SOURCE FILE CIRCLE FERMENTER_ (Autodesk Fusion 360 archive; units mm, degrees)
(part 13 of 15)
sketch "Sketch1" plane through (0, 0, 0) normal (0, 1, 0) x axis (1, 0, 0)
  line L1 (-1.5, 8) -> (-1.5, 0)
  line L2 (0, 8) -> (-1.5, 8)
  line L3 (0, -3) -> (0, 8)
  line L4 (-2.75, 0) -> (-1.5, 0)
  line L5 (-2.75, -3) -> (-2.75, 0)
  line L6 (0, -3) -> (-2.75, -3)
  point P1 (0, 0)
  point P4 (0, 8)
  point P7 (0, -3)
  point P5 (-2.75, 0)
  point P6 (-2.75, -3)
  perpendicular L1 L2
  collinear P1 P4 P7
  perpendicular L1 L4
  coincident P1 L4
  vertical L1
  vertical L3
  parallel L3 L5
  coincident L3 P7
  perpendicular L3 L6
  dimension "d9" = 3 (= "adsk_nomdia")
  dimension "d66" = 5.5 (= "adsk_headdia")
  dimension "d68" distance P1 P4 = 8 (= "adsk_nomlen")
  dimension "d79" distance P5 P6 = 3 (= "adsk_headh")
revolve "Revolve1" sketch "Sketch1" AlongAngle 360
work_plane "WorkPlane1" AlongDistance 3 (= "adsk_headh")
sketch "Sketch6" plane through (0, 0, 3) normal (0, 0, 1) x axis (1, 0, 0)
  line L1 (1.25, 0) -> (-1.25, 0)
  line L2 (-1.25, 0.7217) -> (0, 0)
  line L3 (-1.25, 0.7217) -> (-1.25, -0.7217)
  line L4 (0, 0) -> (-1.25, -0.7217)
  point P1 (0, 0)
  point P4 (0, 0)
  point P2 (-1.25, 0)
  point P5 (-1.25, 0.7217)
  point P7 (-1.25, 0.7217)
  point P8 (0, 0)
  point P3 (1.25, 0)
  horizontal L1
  midpoint P1 L1
  coincident P1 P4
  perpendicular L1 L3
  midpoint P2 L3
  coincident P5 P7
  coincident P1 P8
  dimension "d72" distance P2 P3 = 2.5 (= "adsk_waflat")
  dimension "d100" angle L1 L2 = 150
extrude "Extrude1" cut sketch "Sketch6" profile of L2 L3 L4 no distance stored
circular_pattern "C-Pattern1" TotalAngle 360
extrude "Extrude2" cut of existing geometry no distance stored taper -85
thread "Thread2" ThreadOffset 0 ThreadLength 6.6933 (= "adsk_thrlen")
fillet "Fillet4" radius 0.3 (= "adsk_nomdia * 0.1")
sketch "Sketch7" plane through (0, 0, 0) normal (0, 1, 0) x axis (1, 0, 0)
  line L1 (-1.53, 7.6933) -> (-1.53, 8)
  line L2 (-1.1933, 8) -> (-1.53, 7.6933)
  line L3 (0, -3) -> (0, 8)
  line L4 (0, 8) -> (-1.53, 8)
  point P5 (0, 8)
  point P7 (0, 8)
  point P4 (-1.1933, 8)
  point P3 (-1.53, 7.6933)
  point P1 (0, 0)
  coincident P5 P7
  perpendicular L3 L4
  coincident P4 L4
  perpendicular L1 L4
  dimension "d92" distance P3 P4 = 0.3067 (= "adsk_startlen")
  dimension "d98" distance P1 P4 = 1.1933 (= "adsk_endpointdia / 2")
  dimension "d99" distance P1 L1 = 1.53 (= "adsk_nomdia * 0.51")
revolve "Revolve3" sketch "Sketch7" AlongAngle 360
joint_origin "JointOrigin2" OffsetX 0 OffsetY 0 OffsetZ 0 AngleZ 0

design "ruthex_RX-M3x4"
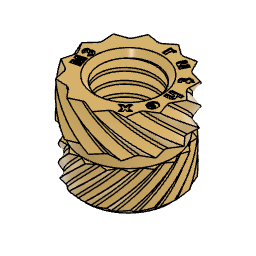
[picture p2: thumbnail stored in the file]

design "PTC"
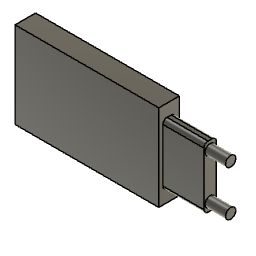
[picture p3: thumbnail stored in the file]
sketch "Schizzo1" plane through (0, 0, 0) normal (0, 1, 0) x axis (1, 0, 0)
  line L1 (35, 0) -> (0, 0)
  line L2 (35, -21) -> (35, 0)
  line L3 (0, -21) -> (35, -21)
  line L4 (0, 0) -> (0, -21)
  point P1 (0, 0)
  point P2 (0, 0)
  point P4 (35, -21)
  point P5 (0, -21)
  horizontal L1
  vertical L2
  horizontal L3
  vertical L4
  coincident P1 P2
  dimension "d19" distance P4 P5 = 35
  dimension "d20" distance P2 P5 = 21
extrude "Estrusione1" new body sketch "Schizzo1" along normal blind 5
sketch "Schizzo2" plane through (35, 0, 0) normal (1, 0, 0) x axis (0, 1, 0)
  line L1 (0, 0) -> (0, 21)
  line L2 (5, 0) -> (0, 0)
  line L3 (5, 21) -> (5, 0)
  line L4 (0, 21) -> (5, 21)
  line L5 (5, 0) -> (0, 21)
  line L6 (0, 0) -> (5, 21)
  line L7 (4, 3) -> (1, 3)
  line L8 (4, 18) -> (4, 3)
  line L9 (1, 18) -> (4, 18)
  line L10 (1, 3) -> (1, 18)
  line L11 (4, 18) -> (1, 3)
  line L12 (1, 18) -> (4, 3)
  point P2 (0, 21)
  point P6 (0, 21)
  point P4 (5, 0)
  point P7 (5, 0)
  point P5 (5, 21)
  point P8 (5, 21)
  point P3 (0, 0)
  point P9 (0, 0)
  point P14 (2.5, 10.5)
  point P10 (1, 3)
  point P11 (4, 3)
  point P13 (1, 18)
  coincident P2 P6
  coincident P4 P7
  coincident P5 P8
  coincident P3 P9
  horizontal L7
  perpendicular L7 L8
  parallel L7 L9
  parallel L8 L10
  coincident L11 P14
  coincident L12 P14
  coincident L5 P14
  coincident L6 P14
  dimension "d23" distance P10 P11 = 3
  dimension "d24" distance P10 P13 = 15
extrude "Estrusione2" add sketch "Schizzo2" profile of L7 L8 L9 L10 along normal blind 10
fillet "Raccordo" radius 1
sketch "Schizzo3" plane through (45, 0, 0) normal (1, 0, 0) x axis (0, 1, 0)
  line L1 (4, 17) -> (4, 4)
  line L2 (2, 18) -> (3, 18)
  line L3 (1, 4) -> (1, 17)
  line L4 (3, 3) -> (2, 3)
  line L5 (2, 4) -> (3, 4)
  line L6 (1, 10.5) -> (4, 10.5)
  line L7 (2.5, 5) -> (2.5, 4)
  arc A1 centre (3, 4) radius 1 clockwise from (4, 4) to (3, 3)
  arc A2 centre (3, 17) radius 1 clockwise from (3, 18) to (4, 17)
  arc A3 centre (2, 17) radius 1 clockwise from (1, 17) to (2, 18)
  arc A4 centre (2, 4) radius 1 clockwise from (2, 3) to (1, 4)
  circle C1 centre (2.5, 5) radius 1.25
  circle C2 centre (2.5, 16) radius 1.25
  point P4 (3, 4)
  point P14 (3, 4)
  point P13 (2, 4)
  point P15 (2, 4)
  point P16 (4, 10.5)
  point P17 (1, 10.5)
  point P19 (2.5, 4)
  point P18 (2.5, 5)
  point P20 (2.5, 5)
  coincident P4 P14
  coincident P13 P15
  midpoint L1 P16
  midpoint L3 P17
  midpoint L5 P19
  coincident P18 P20
  vertical L7
  symmetric L6 C1 C2
  dimension "d29" diameter C1 = 2.5
  dimension "d30" distance P19 P20 = 1
extrude "Estrusione3" add sketch "Schizzo3" profile of C1 C2 along normal blind 5

design "40x40x10 DC Fan"
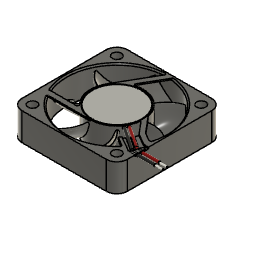
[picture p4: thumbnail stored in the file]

design "GN 1-4 h65.ipt"
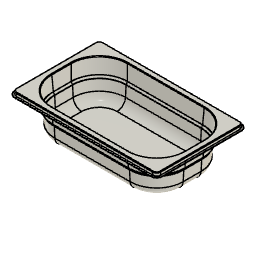
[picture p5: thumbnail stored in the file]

design "Schermo elink"
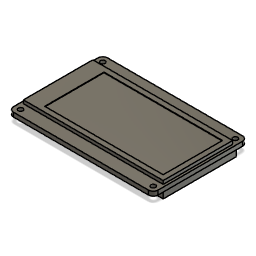
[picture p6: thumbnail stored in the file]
sketch "Schizzo1" plane through (0, 0, 0) normal (0, 1, 0) x axis (1, 0, 0)
  line L1 (-28.5, 19.85) -> (28.5, 19.85)
  line L2 (-30.5, -17.85) -> (-30.5, 17.85)
  line L3 (28.5, -19.85) -> (-28.5, -19.85)
  line L4 (30.5, 17.85) -> (30.5, -17.85)
  line L5 (-30.5, -19.85) -> (30.5, 19.85)
  line L6 (30.5, -19.85) -> (-30.5, 19.85)
  line L7 (28, 17.35) -> (-28, 17.35)
  line L8 (28, -17.35) -> (28, 17.35)
  line L9 (-28, -17.35) -> (28, -17.35)
  line L10 (-28, 17.35) -> (-28, -17.35)
  line L11 (28, -17.35) -> (-28, 17.35)
  line L12 (-28, -17.35) -> (28, 17.35)
  line L13 (29.5, 14.65) -> (-29.5, 14.65)
  line L14 (29.5, -14.65) -> (29.5, 14.65)
  line L15 (-29.5, -14.65) -> (29.5, -14.65)
  line L16 (-29.5, 14.65) -> (-29.5, -14.65)
  line L17 (29.5, -14.65) -> (-29.5, 14.65)
  line L18 (-29.5, -14.65) -> (29.5, 14.65)
  line L19 (-22.65, 12.5) -> (27.35, 12.5)
  line L20 (-22.65, -12.5) -> (-22.65, 12.5)
  line L21 (27.35, -12.5) -> (-22.65, -12.5)
  line L22 (27.35, 12.5) -> (27.35, -12.5)
  circle C1 centre (-28, 17.35) radius 1
  circle C2 centre (28, 17.35) radius 1
  circle C3 centre (-28, -17.35) radius 1
  circle C4 centre (28, -17.35) radius 1
  arc A1 centre (28.5, 17.85) radius 2 clockwise from (28.5, 19.85) to (30.5, 17.85)
  arc A2 centre (28.5, -17.85) radius 2 clockwise from (30.5, -17.85) to (28.5, -19.85)
  arc A3 centre (-28.5, -17.85) radius 2 clockwise from (-28.5, -19.85) to (-30.5, -17.85)
  arc A4 centre (-28.5, 17.85) radius 2 clockwise from (-30.5, 17.85) to (-28.5, 19.85)
  point P6 (0, 0)
  point P1 (0, 0)
  point P11 (0, 0)
  point P7 (-28, 17.35)
  point P12 (-28, 17.35)
  point P20 (0, 0)
  point P2 (30.5, 19.85)
  point P5 (30.5, -19.85)
  point P4 (-30.5, -19.85)
  point P3 (-30.5, 19.85)
  point P16 (-29.5, 14.65)
  point P19 (-29.5, -14.65)
  point P17 (29.5, 14.65)
  point P21 (27.35, 12.5)
  point P22 (-22.65, 12.5)
  point P24 (27.35, -12.5)
  horizontal L1
  perpendicular L1 L2
  parallel L1 L3
  parallel L2 L4
  coincident L5 P6
  coincident L6 P6
  coincident P1 P6
  horizontal L7
  perpendicular L7 L8
  parallel L7 L9
  parallel L8 L10
  coincident L11 P11
  coincident L12 P11
  coincident P1 P11
  coincident P7 P12
  horizontal L13
  perpendicular L13 L14
  parallel L13 L15
  parallel L14 L16
  coincident L17 P20
  coincident L18 P20
  coincident P1 P20
  horizontal L19
  vertical L20
  horizontal L21
  vertical L22
  coincident P2 L1
  coincident P2 L4
  tangent L1 A1
  tangent L4 A1
  coincident P5 L3
  coincident P5 L4
  tangent L3 A2
  tangent L4 A2
  equal A1 A2
  coincident P4 L2
  coincident P4 L3
  tangent L2 A3
  tangent L3 A3
  equal A1 A3
  coincident P3 L2
  coincident P3 L1
  tangent L2 A4
  tangent L1 A4
  equal A1 A4
  dimension "d1" distance P4 P5 = 61
  dimension "d2" distance P2 P5 = 39.7
  dimension "d3" diameter C1 = 2
  dimension "d4" distance L1 P12 = 2.5 (= "d5")
  dimension "d5" distance L2 L10 = 2.5
  dimension "d11" distance P16 P19 = 29.3
  dimension "d12" distance P16 P17 = 59
  dimension "d13" distance P21 P22 = 50
  dimension "d14" distance P21 P24 = 25
  dimension "d15" distance L13 L19 = 2.15
  dimension "d16" distance L14 L22 = 2.15
  dimension "d17" radius A1 = 2
  dimension "d9" R-Pattern1-uDistance = 56
  dimension "d10" R-Pattern1-vDistance = -34.7
extrude "Estrusione1" new body sketch "Schizzo1" profile of L1 L2 L3 L4 C1 C2 C3 C4 L13 L14 L15 L16 L19 L20 L21 L22 A1 A2 A3 A4 against normal blind 1.8 bodies "scheda"
extrude "Estrusione2" new body sketch "Schizzo1" profile of L13 L14 L15 L16 L19 L20 L21 L22 along normal blind 1.4 bodies "Schermo"
extrude "Estrusione3" sketch "Schizzo1" profile of L19 L20 L21 L22 blind -0.2
sketch "Schizzo2" plane through (0, -1.8, 0) normal (0, -1, 0) x axis (1, 0, 0)
  line L1 (28.5, -19.85) -> (-28.5, -19.85)
  line L2 (30.5, 17.85) -> (30.5, -17.85)
  line L3 (-28.5, 19.85) -> (28.5, 19.85)
  line L4 (-30.5, -17.85) -> (-30.5, 17.85)
  line L5 (30.5, 15.6614) -> (-30.5, 15.6614)
  line L6 (30.5, -15.2284) -> (30.5, 15.6614)
  line L7 (-30.5, -15.2284) -> (30.5, -15.2284)
  line L8 (-30.5, 15.6614) -> (-30.5, -15.2284)
  circle C1 centre (28, 17.35) radius 1
  circle C2 centre (-28, 17.35) radius 1
  circle C3 centre (-28, -17.35) radius 1
  circle C4 centre (28, -17.35) radius 1
  arc A1 centre (-28.5, -17.85) radius 2 clockwise from (-28.5, -19.85) to (-30.5, -17.85)
  arc A2 centre (28.5, -17.85) radius 2 clockwise from (30.5, -17.85) to (28.5, -19.85)
  arc A3 centre (28.5, 17.85) radius 2 clockwise from (28.5, 19.85) to (30.5, 17.85)
  arc A4 centre (-28.5, 17.85) radius 2 clockwise from (-30.5, 17.85) to (-28.5, 19.85)
  point P20 (30.5, -15.2284)
  point P18 (-30.5, 15.6614)
  horizontal L5
  vertical L6
  horizontal L7
  vertical L8
  coincident L2 P20
  coincident L4 P18
extrude "Estrusione4" new body sketch "Schizzo2" + "Schizzo1" profile of S1:L2 S1:L4 S1:L5 S1:L6 S1:L7 S1:L8 blind 2.5 bodies "Ingombri lettori sd etc"
named bodies: "scheda", "Ingombri lettori sd etc", "Schermo"

design "DHT22 Module v3"
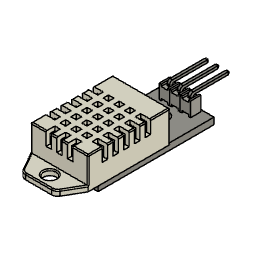
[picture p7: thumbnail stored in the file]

design "MODULO RISCALDATORE 1 ventola" references "PTC", "40x40x10 DC Fan"
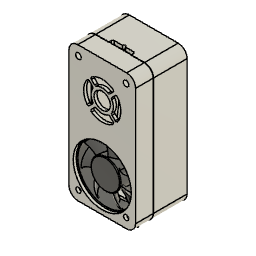
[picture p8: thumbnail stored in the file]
sketch "Schizzo1" plane through (0, 0, 0) normal (0, 1, 0) x axis (1, 0, 0)
  line L1 (40, -20) -> (-40, -20)
  line L2 (40, 20) -> (40, -20)
  line L3 (-40, 20) -> (40, 20)
  line L4 (-40, -20) -> (-40, 20)
  line L5 (40, 20) -> (-40, -20)
  line L6 (-40, 20) -> (40, -20)
  point P6 (0, 0)
  point P1 (0, 0)
  horizontal L1
  perpendicular L1 L2
  parallel L1 L3
  parallel L2 L4
  coincident L5 P6
  coincident L6 P6
  coincident P1 P6
  dimension "d1" distance L2 L4 = 80
  dimension "d2" distance L1 L3 = 40
component_insert "Inserimento componente1"
base_feature "Lavorazione di base1"
joint "Assembla3" alignAngle 0 alignOffsetX 0 alignOffsetY 0 alignOffsetZ 0
sketch "Schizzo3" plane through (0, -5.5864, 0) normal (0, -1, 0) x axis (1, 0, 0)
  line L1 (-79.1534, 19.7854) -> (-47.1534, 19.7854)
  line L2 (-83.1534, -16.2146) -> (-83.1534, 15.7854)
  line L3 (-47.1534, -20.2146) -> (-79.1534, -20.2146)
  line L4 (-43.1534, 15.7854) -> (-43.1534, -16.2146)
  line L5 (-39.1534, 19.7854) -> (-7.1534, 19.7854)
  line L6 (-43.1534, -16.2146) -> (-43.1534, 15.7854)
  line L7 (-7.1534, -20.2146) -> (-39.1534, -20.2146)
  line L8 (-3.1534, 15.7854) -> (-3.1534, -16.2146)
  line L9 (-47.1534, 19.7854) -> (-39.1534, 19.7854)
  line L10 (-47.1534, -20.2146) -> (-39.1534, -20.2146)
  line L11 (-85.1534, -16.2146) -> (-85.1534, 15.7854)
  line L12 (-47.1534, -22.2146) -> (-79.1534, -22.2146)
  line L13 (-47.1534, -22.2146) -> (-39.1534, -22.2146)
  line L14 (-7.1534, -22.2146) -> (-39.1534, -22.2146)
  line L15 (-1.1534, 15.7854) -> (-1.1534, -16.2146)
  line L16 (-39.1534, 21.7854) -> (-7.1534, 21.7854)
  line L17 (-47.1534, 21.7854) -> (-39.1534, 21.7854)
  line L18 (-79.1534, 21.7854) -> (-47.1534, 21.7854)
  line L19 (-1.1534, 67.7854) -> (-1.1534, 15.7854)
  line L20 (-85.1534, 67.7854) -> (-1.1534, 67.7854)
  line L21 (-85.1534, 15.7854) -> (-85.1534, 67.7854)
  arc A1 centre (-47.1534, 15.7854) radius 4 clockwise from (-47.1534, 19.7854) to (-43.1534, 15.7854)
  arc A2 centre (-79.1534, 15.7854) radius 4 clockwise from (-83.1534, 15.7854) to (-79.1534, 19.7854)
  arc A3 centre (-79.1534, -16.2146) radius 4 clockwise from (-79.1534, -20.2146) to (-83.1534, -16.2146)
  arc A4 centre (-47.1534, -16.2146) radius 4 clockwise from (-43.1534, -16.2146) to (-47.1534, -20.2146)
  circle C1 centre (-79.1534, 15.7854) radius 1.725
  circle C2 centre (-79.1534, -16.2146) radius 1.725
  circle C3 centre (-47.1534, -16.2146) radius 1.725
  circle C4 centre (-47.1534, 15.7854) radius 1.725
  circle C5 centre (-63.1534, -0.2146) radius 19.5
  arc A5 centre (-7.1534, 15.7854) radius 4 clockwise from (-7.1534, 19.7854) to (-3.1534, 15.7854)
  arc A6 centre (-39.1534, 15.7854) radius 4 clockwise from (-43.1534, 15.7854) to (-39.1534, 19.7854)
  arc A7 centre (-39.1534, -16.2146) radius 4 clockwise from (-39.1534, -20.2146) to (-43.1534, -16.2146)
  arc A8 centre (-7.1534, -16.2146) radius 4 clockwise from (-3.1534, -16.2146) to (-7.1534, -20.2146)
  circle C6 centre (-39.1534, 15.7854) radius 1.725
  circle C7 centre (-39.1534, -16.2146) radius 1.725
  circle C8 centre (-7.1534, -16.2146) radius 1.725
  circle C9 centre (-7.1534, 15.7854) radius 1.725
  circle C10 centre (-23.1534, -0.2146) radius 19.5
  arc A9 centre (-79.1534, -16.2146) radius 6 clockwise from (-79.1534, -22.2146) to (-85.1534, -16.2146)
  arc A10 centre (-7.1534, -16.2146) radius 6 clockwise from (-1.1534, -16.2146) to (-7.1534, -22.2146)
  point P18 (-39.1534, 19.7854)
  point P28 (-39.1534, 19.7854)
  point P3 (-47.1534, 19.7854)
  point P29 (-47.1534, 19.7854)
  point P22 (-39.1534, -20.2146)
  point P30 (-39.1534, -20.2146)
  point P11 (-47.1534, -20.2146)
  point P31 (-47.1534, -20.2146)
  coincident P18 P28
  coincident P3 P29
  coincident P22 P30
  coincident P11 P31
  concentric A3 A9
  concentric A8 A10
  tangent A9 L12
  tangent L11 A9
  tangent L14 A10
  tangent A10 L15
  parallel L15 L19
  perpendicular L19 L20
  vertical L21
  dimension "d32" distance L12 L20 = 90
extrude "Estrusione2" new body sketch "Schizzo3" profile of A1 L1 A2 L2 A3 L3 A4 L4 C1 C2 C3 C4 C5 A5 L5 A6 L6 A7 L7 A8 L8 C6 C7 C8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 along normal blind 2
fillet "Raccordo1" radius 6
sketch "Schizzo4" plane through (0, -5.5864, 0) normal (0, 1, 0) x axis (-1, 0, 0)
  line L1 (1.1534, -16.2146) -> (1.1534, 61.7854)
  line L2 (79.1534, -22.2146) -> (7.1534, -22.2146)
  line L3 (85.1534, 61.7854) -> (85.1534, -16.2146)
  line L4 (7.1534, 67.7854) -> (79.1534, 67.7854)
  line L5 (7.1534, 65.7854) -> (79.1534, 65.7854)
  line L6 (3.1534, -16.2146) -> (3.1534, 61.7854)
  line L7 (79.1534, -20.2146) -> (7.1534, -20.2146)
  line L8 (83.1534, 61.7854) -> (83.1534, -16.2146)
  circle C1 centre (7.1534, -16.2146) radius 1.725
  circle C2 centre (23.1534, -0.2146) radius 19.5
  circle C3 centre (63.1534, -0.2146) radius 19.5
  circle C4 centre (79.1534, -16.2146) radius 1.725
  arc A1 centre (7.1534, 61.7854) radius 6 clockwise from (1.1534, 61.7854) to (7.1534, 67.7854)
  arc A2 centre (7.1534, -16.2146) radius 6 clockwise from (7.1534, -22.2146) to (1.1534, -16.2146)
  arc A3 centre (79.1534, -16.2146) radius 6 clockwise from (85.1534, -16.2146) to (79.1534, -22.2146)
  arc A4 centre (79.1534, 61.7854) radius 6 clockwise from (79.1534, 67.7854) to (85.1534, 61.7854)
  arc A5 centre (7.1534, 61.7854) radius 4 clockwise from (3.1534, 61.7854) to (7.1534, 65.7854)
  arc A6 centre (7.1534, -16.2146) radius 4 clockwise from (7.1534, -20.2146) to (3.1534, -16.2146)
  arc A7 centre (79.1534, -16.2146) radius 4 clockwise from (83.1534, -16.2146) to (79.1534, -20.2146)
  arc A8 centre (79.1534, 61.7854) radius 4 clockwise from (79.1534, 65.7854) to (83.1534, 61.7854)
  dimension "d37" = -2
extrude "Estrusione3" add sketch "Schizzo4" profile of A1 L1 A2 L2 A3 L3 A4 L4 L5 A8 L7 A5 L6 A6 L8 A7 along normal blind 25
component_insert "Inserimento componente3"
joint "Assembla4" alignAngle 180 alignOffsetX 0 alignOffsetY 0 alignOffsetZ 5
sketch "Schizzo5" plane through (0, -5.5864, 0) normal (0, 1, 0) x axis (-1, 0, 0)
  line L1 (7.1534, 65.7854) -> (79.1534, 65.7854)
  line L2 (3.1534, -16.2146) -> (3.1534, 61.7854)
  line L3 (79.1534, -20.2146) -> (7.1534, -20.2146)
  line L4 (83.1534, 61.7854) -> (83.1534, -16.2146)
  line L5 (47.1534, 19.7854) -> (79.1534, 19.7854)
  line L6 (7.1534, 19.7854) -> (39.1534, 19.7854)
  arc A1 centre (7.1534, 61.7854) radius 4 clockwise from (3.1534, 61.7854) to (7.1534, 65.7854)
  arc A2 centre (7.1534, -16.2146) radius 4 clockwise from (7.1534, -20.2146) to (3.1534, -16.2146)
  arc A3 centre (79.1534, -16.2146) radius 4 clockwise from (83.1534, -16.2146) to (79.1534, -20.2146)
  arc A4 centre (79.1534, 61.7854) radius 4 clockwise from (79.1534, 65.7854) to (83.1534, 61.7854)
  circle C1 centre (7.1534, -16.2146) radius 1.725
  circle C2 centre (63.1534, -0.2146) radius 19.5
  circle C3 centre (79.1534, -16.2146) radius 1.725
  circle C4 centre (23.1534, -0.2146) radius 19.5
sketch "Schizzo6" plane through (0, 0, 67.7854) normal (0, 0, 1) x axis (-1, 0, 0)
  line L1 (7.1534, -19.4136) -> (7.1534, 7.5864)
  line L2 (79.1534, -19.4136) -> (7.1534, -19.4136)
  line L3 (79.1534, 7.5864) -> (79.1534, -19.4136)
  line L4 (7.1534, 7.5864) -> (79.1534, 7.5864)
  line L5 (49.6534, -7.4136) -> (36.6534, -7.4136)
  line L6 (50.6534, -5.4136) -> (50.6534, -6.4136)
  line L7 (36.6534, -4.4136) -> (49.6534, -4.4136)
  line L8 (35.6534, -6.4136) -> (35.6534, -5.4136)
  line L9 (50.6534, -19.4136) -> (50.6534, -6.4136)
  line L10 (35.6534, -19.4136) -> (35.6534, -6.4136)
  circle C1 centre (48.6534, -5.9136) radius 1.25
  circle C2 centre (37.6534, -5.9136) radius 1.25
  arc A1 centre (36.6534, -6.4136) radius 1 clockwise from (36.6534, -7.4136) to (35.6534, -6.4136)
  arc A2 centre (49.6534, -6.4136) radius 1 clockwise from (50.6534, -6.4136) to (49.6534, -7.4136)
  arc A3 centre (49.6534, -5.4136) radius 1 clockwise from (49.6534, -4.4136) to (50.6534, -5.4136)
  arc A4 centre (36.6534, -5.4136) radius 1 clockwise from (35.6534, -5.4136) to (36.6534, -4.4136)
  point P12 (50.6534, -6.4136)
  point P20 (50.6534, -6.4136)
  point P21 (50.6534, -19.4136)
  point P8 (35.6534, -6.4136)
  point P22 (35.6534, -6.4136)
  point P23 (35.6534, -19.4136)
  coincident P12 P20
  coincident L2 P21
  tangent A2 L9
  coincident P8 P22
  coincident L2 P23
  tangent A1 L10
extrude "Estrusione4" cut sketch "Schizzo6" profile of L2 C1 C2 A1 L5 A2 L6 A3 L7 A4 L8 L9 L10 against normal blind 5.599
extrude "Estrusione5" cut of existing geometry blind -14
sketch "Schizzo7" plane through (0, -7.5864, 0) normal (0, -1, 0) x axis (1, 0, 0)
  line L1 (-79.1534, 67.7854) -> (-7.1534, 67.7854)
  line L2 (-85.1534, -16.2146) -> (-85.1534, 61.7854)
  line L3 (-7.1534, -22.2146) -> (-79.1534, -22.2146)
  line L4 (-1.1534, 61.7854) -> (-1.1534, -16.2146)
  line L5 (-43.1534, -22.2146) -> (-43.1534, 67.7854)
  line L6 (-23.1534, 31.2854) -> (-63.1534, 31.2854)
  line L7 (-63.1534, 56.2854) -> (-23.1534, 56.2854)
  line L8 (-23.1534, 43.7854) -> (-63.1534, 43.7854)
  arc A1 centre (-7.1534, 61.7854) radius 6 clockwise from (-7.1534, 67.7854) to (-1.1534, 61.7854)
  arc A2 centre (-79.1534, 61.7854) radius 6 clockwise from (-85.1534, 61.7854) to (-79.1534, 67.7854)
  arc A3 centre (-79.1534, -16.2146) radius 6 clockwise from (-79.1534, -22.2146) to (-85.1534, -16.2146)
  arc A4 centre (-7.1534, -16.2146) radius 6 clockwise from (-1.1534, -16.2146) to (-7.1534, -22.2146)
  circle C1 centre (-7.1534, -16.2146) radius 1.725
  circle C2 centre (-63.1534, -0.2146) radius 19.5
  circle C3 centre (-79.1534, -16.2146) radius 1.725
  circle C4 centre (-23.1534, -0.2146) radius 19.5
  arc A5 centre (-23.1534, 43.7854) radius 12.5 clockwise from (-23.1534, 56.2854) to (-23.1534, 31.2854)
  arc A6 centre (-63.1534, 43.7854) radius 12.5 clockwise from (-63.1534, 31.2854) to (-63.1534, 56.2854)
  point P16 (-43.1534, 67.7854)
  point P17 (-43.1534, -22.2146)
  point P24 (-43.1534, 43.7854)
  point P23 (-23.1534, 43.7854)
  midpoint L1 P16
  midpoint L3 P17
  tangent L6 A5
  tangent A5 L7
  parallel L6 L7
  tangent L7 A6
  tangent L6 A6
  perpendicular L5 L8
  coincident L5 P24
  midpoint L8 P24
  dimension "d48" distance L6 L7 = 25
  dimension "d49" distance L5 P23 = 20
  dimension "d50" distance L1 P24 = 24
extrude "Estrusione6" cut sketch "Schizzo7" profile of L6 A5 L7 A6 against normal blind 2
sketch "Schizzo8" plane through (0, -7.5864, 0) normal (0, -1, 0) x axis (1, 0, 0)
  line L1 (-63.1534, 31.2854) -> (-23.1534, 31.2854)
  line L2 (-23.1534, 56.2854) -> (-63.1534, 56.2854)
  line L3 (-79.1534, 67.7854) -> (-7.1534, 67.7854)
  line L4 (-85.1534, -16.2146) -> (-85.1534, 61.7854)
  line L5 (-7.1534, -22.2146) -> (-79.1534, -22.2146)
  line L6 (-1.1534, 61.7854) -> (-1.1534, -16.2146)
  line L7 (-23.1534, 51.2854) -> (-63.1534, 51.2854)
  line L8 (-63.1534, 36.2854) -> (-23.1534, 36.2854)
  line L9 (-23.1534, 49.2854) -> (-63.1534, 49.2854)
  line L10 (-63.1534, 38.2854) -> (-23.1534, 38.2854)
  line L11 (-43.1534, 56.2854) -> (-43.1534, 51.2854)
  line L12 (-42.1534, 56.2854) -> (-42.1534, 51.2854)
  line L13 (-44.1534, 56.2854) -> (-44.1534, 51.2854)
  line L14 (-63.1534, 43.7854) -> (-23.1534, 43.7854)
  line L15 (-71.9922, 52.6243) -> (-63.1534, 43.7854)
  line L16 (-50.6534, 43.7854) -> (-63.1534, 43.7854)
  line L17 (-71.2568, 53.3031) -> (-67.7022, 49.7485)
  line L18 (-72.671, 51.8888) -> (-69.1164, 48.3343)
  line L19 (-54.1534, 51.2854) -> (-56.1534, 51.2854)
  line L20 (-54.1534, 56.2854) -> (-54.1534, 51.2854)
  line L21 (-56.1534, 56.2854) -> (-54.1534, 56.2854)
  line L22 (-56.1534, 51.2854) -> (-56.1534, 56.2854)
  line L23 (-15.05, 53.3031) -> (-18.6045, 49.7485)
  line L24 (-13.6358, 51.8888) -> (-17.1903, 48.3343)
  line L25 (-30.1534, 51.2854) -> (-30.1534, 56.2854)
  line L26 (-32.1534, 56.2854) -> (-32.1534, 51.2854)
  line L27 (-44.1534, 31.2854) -> (-44.1534, 36.2854)
  line L28 (-42.1534, 31.2854) -> (-42.1534, 36.2854)
  line L29 (-32.1534, 31.2854) -> (-32.1534, 36.2854)
  line L30 (-30.1534, 36.2854) -> (-30.1534, 31.2854)
  line L31 (-15.05, 34.2678) -> (-18.6045, 37.8224)
  line L32 (-13.6358, 35.682) -> (-17.1903, 39.2366)
  line L33 (-54.1534, 31.2854) -> (-54.1534, 36.2854)
  line L34 (-56.1534, 36.2854) -> (-56.1534, 31.2854)
  line L35 (-71.2568, 34.2678) -> (-67.7022, 37.8224)
  line L36 (-72.671, 35.682) -> (-69.1164, 39.2366)
  arc A1 centre (-63.1534, 43.7854) radius 12.5 clockwise from (-63.1534, 31.2854) to (-63.1534, 56.2854)
  arc A2 centre (-23.1534, 43.7854) radius 12.5 clockwise from (-23.1534, 56.2854) to (-23.1534, 31.2854)
  arc A3 centre (-7.1534, 61.7854) radius 6 clockwise from (-7.1534, 67.7854) to (-1.1534, 61.7854)
  arc A4 centre (-79.1534, 61.7854) radius 6 clockwise from (-85.1534, 61.7854) to (-79.1534, 67.7854)
  arc A5 centre (-79.1534, -16.2146) radius 6 clockwise from (-79.1534, -22.2146) to (-85.1534, -16.2146)
  arc A6 centre (-7.1534, -16.2146) radius 6 clockwise from (-1.1534, -16.2146) to (-7.1534, -22.2146)
  circle C1 centre (-7.1534, -16.2146) radius 1.725
  circle C2 centre (-63.1534, -0.2146) radius 19.5
  circle C3 centre (-79.1534, -16.2146) radius 1.725
  circle C4 centre (-23.1534, -0.2146) radius 19.5
  arc A7 centre (-23.1534, 43.7854) radius 7.5 clockwise from (-23.1534, 51.2854) to (-23.1534, 36.2854)
  arc A8 centre (-63.1534, 43.7854) radius 7.5 clockwise from (-63.1534, 36.2854) to (-63.1534, 51.2854)
  arc A9 centre (-23.1534, 43.7854) radius 5.5 clockwise from (-23.1534, 49.2854) to (-23.1534, 38.2854)
  arc A10 centre (-63.1534, 43.7854) radius 5.5 clockwise from (-63.1534, 38.2854) to (-63.1534, 49.2854)
  point P34 (-43.1534, 51.2854)
  point P35 (-43.1534, 56.2854)
  point P36 (-42.1534, 51.2854)
  point P37 (-42.1534, 56.2854)
  point P38 (-44.1534, 51.2854)
  point P39 (-44.1534, 56.2854)
  point P7 (-23.1534, 43.7854)
  point P40 (-23.1534, 43.7854)
  point P5 (-63.1534, 43.7854)
  point P41 (-63.1534, 43.7854)
  point P42 (-63.1534, 43.7854)
  point P45 (-67.7022, 49.7485)
  point P46 (-71.2568, 53.3031)
  point P47 (-69.1164, 48.3343)
  point P48 (-72.671, 51.8888)
  point P51 (-54.1534, 56.2854)
  point P49 (-56.1534, 51.2854)
  point P53 (-18.6045, 49.7485)
  point P54 (-15.05, 53.3031)
  point P55 (-17.1903, 48.3343)
  point P56 (-13.6358, 51.8888)
  point P58 (-30.1534, 51.2854)
  point P50 (-54.1534, 51.2854)
  point P59 (-32.1534, 51.2854)
  point P60 (-32.1534, 56.2854)
  point P52 (-56.1534, 56.2854)
  point P57 (-30.1534, 56.2854)
  point P63 (-42.1534, 36.2854)
  point P64 (-42.1534, 31.2854)
  point P61 (-44.1534, 36.2854)
  point P62 (-44.1534, 31.2854)
  point P77 (-67.7022, 37.8224)
  point P78 (-71.2568, 34.2678)
  point P79 (-69.1164, 39.2366)
  point P80 (-72.671, 35.682)
  point P76 (-56.1534, 36.2854)
  point P73 (-54.1534, 36.2854)
  point P74 (-54.1534, 31.2854)
  point P75 (-56.1534, 31.2854)
  point P69 (-18.6045, 37.8224)
  point P70 (-15.05, 34.2678)
  point P71 (-17.1903, 39.2366)
  point P72 (-13.6358, 35.682)
  point P67 (-30.1534, 31.2854)
  point P68 (-30.1534, 36.2854)
  point P65 (-32.1534, 36.2854)
  point P66 (-32.1534, 31.2854)
  midpoint L7 P34
  midpoint L2 P35
  perpendicular L2 L11
  coincident L7 P36
  coincident L2 P37
  perpendicular L2 L12
  coincident L7 P38
  coincident L2 P39
  perpendicular L2 L13
  coincident P7 P40
  coincident P5 P41
  horizontal L16
  coincident P5 P42
  coincident A8 P45
  coincident A1 P46
  coincident A8 P47
  coincident A1 P48
  parallel L15 L18
  parallel L15 L17
  horizontal L19
  vertical L20
  horizontal L21
  vertical L22
  coincident L2 P51
  coincident L7 P49
  symmetric L11 P45 P53
  symmetric L11 P46 P54
  symmetric L11 P47 P55
  symmetric L11 P48 P56
  symmetric L11 P49 P58
  symmetric L11 P50 P59
  symmetric L11 P51 P60
  symmetric L11 P52 P57
  symmetric P36 L14 P63
  symmetric P37 L14 P64
  symmetric P38 L14 P61
  symmetric P39 L14 P62
  symmetric L14 P45 P77
  symmetric L14 P46 P78
  symmetric L14 P47 P79
  symmetric L14 P48 P80
  symmetric L14 P49 P76
  symmetric L14 P50 P73
  symmetric L14 P51 P74
  symmetric L14 P52 P75
  symmetric L14 P53 P69
  symmetric L14 P54 P70
  symmetric L14 P55 P71
  symmetric L14 P56 P72
  symmetric L14 P57 P67
  symmetric L14 P58 P68
  symmetric L14 P59 P65
  symmetric L14 P60 P66
  dimension "d53" = -5
  dimension "d54" = -7
  dimension "d55" distance L11 L13 = 1
  dimension "d56" distance L11 L12 = 1 (= "d55")
  dimension "d57" angle L15 L16 = 135
  dimension "d58" distance L17 L18 = 2
  dimension "d59" distance L15 L17 = 1
  dimension "d60" distance L20 L22 = 2
  dimension "d61" distance L12 L20 = 12
extrude "Estrusione7" add sketch "Schizzo8" profile of L1 A1 L2 A2 L7 A7 L8 A8 L9 A9 L10 A10 L17 L18 L19 L20 L21 L22 L23 L24 L25 L26 L29 L30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 against normal blind 2
fillet "Raccordo2" radius 1
offset_faces "FacceDiOffset" distance 0.4
sketch "Schizzo9" plane through (0, -5.5864, 0) normal (0, 1, 0) x axis (-1, 0, 0)
  line L1 (57.1534, 31.2854) -> (63.1534, 31.2854)
  curve K1 (57.1534, 31.2854) -> (56.1534, 32.2854)
  line L2 (56.1534, 35.2854) -> (56.1534, 32.2854)
  curve K2 (56.1534, 35.2854) -> (57.1534, 36.2854)
  line L3 (63.1534, 36.2854) -> (57.1534, 36.2854)
  curve K3 (67.0599, 37.3832) -> (68.2879, 37.2367)
  line L4 (70.4541, 35.0705) -> (68.2879, 37.2367)
  curve K4 (70.4541, 35.0705) -> (70.3203, 33.5441)
  line L5 (33.1534, 31.2854) -> (53.1534, 31.2854)
  curve K5 (33.1534, 31.2854) -> (32.1534, 32.2854)
  line L6 (32.1534, 35.2854) -> (32.1534, 32.2854)
  curve K6 (32.1534, 35.2854) -> (33.1534, 36.2854)
  line L7 (53.1534, 36.2854) -> (33.1534, 36.2854)
  curve K7 (53.1534, 36.2854) -> (54.1534, 35.2854)
  line L8 (54.1534, 32.2854) -> (54.1534, 35.2854)
  curve K8 (54.1534, 32.2854) -> (53.1534, 31.2854)
  line L9 (23.1534, 31.2854) -> (29.1534, 31.2854)
  curve K9 (15.9864, 33.5441) -> (15.8527, 35.0705)
  line L10 (18.0188, 37.2367) -> (15.8527, 35.0705)
  curve K10 (18.0188, 37.2367) -> (19.2468, 37.3832)
  line L11 (29.1534, 36.2854) -> (23.1534, 36.2854)
  curve K11 (29.1534, 36.2854) -> (30.1534, 35.2854)
  line L12 (30.1534, 32.2854) -> (30.1534, 35.2854)
  curve K12 (30.1534, 32.2854) -> (29.1534, 31.2854)
  curve K13 (12.912, 50.9524) -> (14.4385, 51.0862)
  line L13 (16.6046, 48.92) -> (14.4385, 51.0862)
  curve K14 (16.6046, 48.92) -> (16.7511, 47.692)
  curve K15 (16.7511, 39.8789) -> (16.6046, 38.6509)
  line L14 (14.4385, 36.4847) -> (16.6046, 38.6509)
  curve K16 (14.4385, 36.4847) -> (12.912, 36.6185)
  line L15 (29.1534, 56.2854) -> (23.1534, 56.2854)
  curve K17 (29.1534, 56.2854) -> (30.1534, 55.2854)
  line L16 (30.1534, 52.2854) -> (30.1534, 55.2854)
  curve K18 (30.1534, 52.2854) -> (29.1534, 51.2854)
  line L17 (23.1534, 51.2854) -> (29.1534, 51.2854)
  curve K19 (19.2468, 50.1877) -> (18.0188, 50.3342)
  line L18 (15.8527, 52.5004) -> (18.0188, 50.3342)
  curve K20 (15.8527, 52.5004) -> (15.9864, 54.0268)
  line L19 (53.1534, 56.2854) -> (33.1534, 56.2854)
  curve K21 (53.1534, 56.2854) -> (54.1534, 55.2854)
  line L20 (54.1534, 52.2854) -> (54.1534, 55.2854)
  curve K22 (54.1534, 52.2854) -> (53.1534, 51.2854)
  line L21 (33.1534, 51.2854) -> (53.1534, 51.2854)
  curve K23 (33.1534, 51.2854) -> (32.1534, 52.2854)
  line L22 (32.1534, 55.2854) -> (32.1534, 52.2854)
  curve K24 (32.1534, 55.2854) -> (33.1534, 56.2854)
  line L23 (63.1534, 56.2854) -> (57.1534, 56.2854)
  curve K25 (70.3203, 54.0268) -> (70.4541, 52.5004)
  line L24 (68.2879, 50.3342) -> (70.4541, 52.5004)
  curve K26 (68.2879, 50.3342) -> (67.0599, 50.1877)
  line L25 (57.1534, 51.2854) -> (63.1534, 51.2854)
  curve K27 (57.1534, 51.2854) -> (56.1534, 52.2854)
  line L26 (56.1534, 55.2854) -> (56.1534, 52.2854)
  curve K28 (56.1534, 55.2854) -> (57.1534, 56.2854)
  line L27 (63.1534, 49.2854) -> (23.1534, 49.2854)
  line L28 (23.1534, 38.2854) -> (63.1534, 38.2854)
  line L29 (69.7021, 38.6509) -> (71.8683, 36.4847)
  curve K29 (69.7021, 38.6509) -> (69.5556, 39.8789)
  curve K30 (69.5556, 47.692) -> (69.7021, 48.92)
  line L30 (71.8683, 51.0862) -> (69.7021, 48.92)
  curve K31 (71.8683, 51.0862) -> (73.3947, 50.9524)
  curve K32 (73.3947, 36.6185) -> (71.8683, 36.4847)
  line L31 (7.1534, 65.7854) -> (79.1534, 65.7854)
  line L32 (3.1534, -16.2146) -> (3.1534, 61.7854)
  line L33 (79.1534, -20.2146) -> (7.1534, -20.2146)
  line L34 (83.1534, 61.7854) -> (83.1534, -16.2146)
  line L35 (3.1534, 22.7854) -> (83.1534, 22.7854)
  arc A1 centre (63.1534, 43.7854) radius 12.5 clockwise from (70.3203, 33.5441) to (63.1534, 31.2854)
  arc A2 centre (63.1534, 43.7854) radius 7.5 clockwise from (67.0599, 37.3832) to (63.1534, 36.2854)
  arc A3 centre (23.1534, 43.7854) radius 12.5 clockwise from (23.1534, 31.2854) to (15.9864, 33.5441)
  arc A4 centre (23.1534, 43.7854) radius 7.5 clockwise from (23.1534, 36.2854) to (19.2468, 37.3832)
  arc A5 centre (23.1534, 43.7854) radius 12.5 clockwise from (12.912, 36.6185) to (12.912, 50.9524)
  arc A6 centre (23.1534, 43.7854) radius 7.5 clockwise from (16.7511, 39.8789) to (16.7511, 47.692)
  arc A7 centre (23.1534, 43.7854) radius 12.5 clockwise from (15.9864, 54.0268) to (23.1534, 56.2854)
  arc A8 centre (23.1534, 43.7854) radius 7.5 clockwise from (19.2468, 50.1877) to (23.1534, 51.2854)
  arc A9 centre (63.1534, 43.7854) radius 12.5 clockwise from (63.1534, 56.2854) to (70.3203, 54.0268)
  arc A10 centre (63.1534, 43.7854) radius 7.5 clockwise from (63.1534, 51.2854) to (67.0599, 50.1877)
  arc A11 centre (23.1534, 43.7854) radius 5.5 clockwise from (23.1534, 38.2854) to (23.1534, 49.2854)
  arc A12 centre (63.1534, 43.7854) radius 5.5 clockwise from (63.1534, 49.2854) to (63.1534, 38.2854)
  arc A13 centre (63.1534, 43.7854) radius 7.5 clockwise from (69.5556, 47.692) to (69.5556, 39.8789)
  arc A14 centre (63.1534, 43.7854) radius 12.5 clockwise from (73.3947, 50.9524) to (73.3947, 36.6185)
  arc A15 centre (7.1534, 61.7854) radius 4 clockwise from (3.1534, 61.7854) to (7.1534, 65.7854)
  arc A16 centre (7.1534, -16.2146) radius 4 clockwise from (7.1534, -20.2146) to (3.1534, -16.2146)
  arc A17 centre (79.1534, -16.2146) radius 4 clockwise from (83.1534, -16.2146) to (79.1534, -20.2146)
  arc A18 centre (79.1534, 61.7854) radius 4 clockwise from (79.1534, 65.7854) to (83.1534, 61.7854)
  circle C1 centre (7.1534, -16.2146) radius 1.725
  circle C2 centre (63.1534, -0.2146) radius 19.5
  circle C3 centre (79.1534, -16.2146) radius 1.725
  circle C4 centre (23.1534, -0.2146) radius 19.5
  circle C5 centre (7.1534, -16.2146) radius 1.725
  circle C6 centre (79.1534, -16.2146) radius 1.725
  circle C7 centre (79.1534, 61.7854) radius 1.725
  circle C8 centre (7.1534, 61.7854) radius 1.875
  circle C9 centre (79.1534, 61.7854) radius 1.875
  circle C10 centre (79.1534, 61.7854) radius 4
  circle C11 centre (7.1534, 61.7854) radius 4
  point P96 (83.1534, 22.7854)
  point P97 (3.1534, 22.7854)
  point P94 (7.1534, -16.2146)
  point P98 (7.1534, 61.7854)
  midpoint L34 P96
  midpoint L32 P97
  symmetric C3 L35 C7
  symmetric P94 L35 P98
  concentric A15 C8
  concentric A18 C9
  concentric A18 C10
  concentric A15 C11
  dimension "d67" diameter C8 = 3.75
  dimension "d68" diameter C9 = 3.75
  dimension "d69" diameter C11 = 8
  dimension "d70" diameter C10 = 8
extrude "Estrusione8" add sketch "Schizzo9" profile of A15 A18 C8 C9 C10 C11 along normal blind 11
fillet "Raccordo3" radius 4
extrude "Estrusione9" new body of existing geometry blind 20
sketch "Schizzo10" plane through (0, 25.4136, 0) normal (0, 1, 0) x axis (-1, 0, 0)
  line L1 (85.5534, 62.1854) -> (85.5534, -16.6146)
  line L2 (50.6534, 68.1854) -> (79.5534, 68.1854)
  line L3 (50.6534, 65.7854) -> (50.6534, 68.1854)
  line L4 (71.1534, 65.7854) -> (50.6534, 65.7854)
  line L5 (83.1534, -16.2146) -> (83.1534, 53.7854)
  line L6 (7.1534, -20.2146) -> (79.1534, -20.2146)
  line L7 (3.1534, 53.7854) -> (3.1534, -16.2146)
  line L8 (35.6534, 65.7854) -> (15.1534, 65.7854)
  line L9 (35.6534, 68.1854) -> (35.6534, 65.7854)
  line L10 (6.7534, 68.1854) -> (35.6534, 68.1854)
  line L11 (0.7534, -16.6146) -> (0.7534, 62.1854)
  line L12 (79.5534, -22.6146) -> (6.7534, -22.6146)
  line L13 (0.7534, 22.7854) -> (85.5534, 22.7854)
  circle C1 centre (79.1534, 61.7854) radius 1.875
  circle C2 centre (7.1534, 61.7854) radius 1.875
  arc A1 centre (79.5534, -16.6146) radius 6 clockwise from (85.5534, -16.6146) to (79.5534, -22.6146)
  arc A2 centre (79.5534, 62.1854) radius 6 clockwise from (79.5534, 68.1854) to (85.5534, 62.1854)
  arc A3 centre (71.1534, 61.7854) radius 4 clockwise from (71.1534, 65.7854) to (75.1534, 61.7854)
  arc A4 centre (79.1534, 61.7854) radius 4 clockwise from (79.1534, 57.7854) to (75.1534, 61.7854)
  arc A5 centre (79.1534, 53.7854) radius 4 clockwise from (79.1534, 57.7854) to (83.1534, 53.7854)
  arc A6 centre (79.1534, -16.2146) radius 4 clockwise from (83.1534, -16.2146) to (79.1534, -20.2146)
  arc A7 centre (7.1534, -16.2146) radius 4 clockwise from (7.1534, -20.2146) to (3.1534, -16.2146)
  arc A8 centre (7.1534, 53.7854) radius 4 clockwise from (3.1534, 53.7854) to (7.1534, 57.7854)
  arc A9 centre (7.1534, 61.7854) radius 4 clockwise from (11.1534, 61.7854) to (7.1534, 57.7854)
  arc A10 centre (15.1534, 61.7854) radius 4 clockwise from (11.1534, 61.7854) to (15.1534, 65.7854)
  arc A11 centre (6.7534, 62.1854) radius 6 clockwise from (0.7534, 62.1854) to (6.7534, 68.1854)
  arc A12 centre (6.7534, -16.6146) radius 6 clockwise from (6.7534, -22.6146) to (0.7534, -16.6146)
  arc A13 centre (7.1534, -8.2146) radius 4 clockwise from (7.1534, -12.2146) to (3.1534, -8.2146)
  arc A14 centre (7.1534, -16.2146) radius 4 clockwise from (7.1534, -12.2146) to (11.1534, -16.2146)
  arc A15 centre (15.1534, -16.2146) radius 4 clockwise from (15.1534, -20.2146) to (11.1534, -16.2146)
  arc A16 centre (71.1534, -16.2146) radius 4 clockwise from (75.1534, -16.2146) to (71.1534, -20.2146)
  arc A17 centre (79.1534, -16.2146) radius 4 clockwise from (75.1534, -16.2146) to (79.1534, -12.2146)
  arc A18 centre (79.1534, -8.2146) radius 4 clockwise from (83.1534, -8.2146) to (79.1534, -12.2146)
  point P38 (85.5534, 22.7854)
  point P39 (0.7534, 22.7854)
  point P12 (71.1534, 65.7854)
  point P49 (71.1534, -20.2146)
  point P13 (75.1534, 61.7854)
  point P48 (75.1534, -16.2146)
  point P15 (79.1534, 57.7854)
  point P51 (79.1534, -12.2146)
  point P16 (83.1534, 53.7854)
  point P53 (83.1534, -8.2146)
  point P24 (3.1534, 53.7854)
  point P42 (3.1534, -8.2146)
  point P25 (7.1534, 57.7854)
  point P41 (7.1534, -12.2146)
  point P27 (11.1534, 61.7854)
  point P44 (11.1534, -16.2146)
  point P28 (15.1534, 65.7854)
  point P46 (15.1534, -20.2146)
  midpoint L1 P38
  midpoint L11 P39
  symmetric P12 L13 P49
  symmetric P13 L13 P48
  symmetric A3 L13 A16
  symmetric P15 L13 P51
  symmetric A4 L13 A17
  symmetric P16 L13 P53
  symmetric A5 L13 A18
  symmetric P24 L13 P42
  symmetric P25 L13 P41
  symmetric A8 L13 A13
  symmetric P27 L13 P44
  symmetric A9 L13 A14
  symmetric P28 L13 P46
  symmetric A10 L13 A15
extrude "Estrusione10" add sketch "Schizzo10" profile of L5 A6 L6 A7 L7 A13 A14 A15 A16 A17 A18 against normal blind 20
extrude "Estrusione11" cut of existing geometry blind -11.284
sketch "Schizzo11" plane through (0, 25.4136, 0) normal (0, 1, 0) x axis (-1, 0, 0)
  line L1 (85.5534, 62.1854) -> (85.5534, -16.6146)
  line L2 (50.6534, 68.1854) -> (79.5534, 68.1854)
  line L3 (50.6534, 65.7854) -> (50.6534, 68.1854)
  line L4 (71.1534, 65.7854) -> (50.6534, 65.7854)
  line L5 (83.1534, -8.2146) -> (83.1534, 53.7854)
  line L6 (15.1534, -20.2146) -> (71.1534, -20.2146)
  line L7 (3.1534, 53.7854) -> (3.1534, -8.2146)
  line L8 (35.6534, 65.7854) -> (15.1534, 65.7854)
  line L9 (35.6534, 68.1854) -> (35.6534, 65.7854)
  line L10 (6.7534, 68.1854) -> (35.6534, 68.1854)
  line L11 (0.7534, -16.6146) -> (0.7534, 62.1854)
  line L12 (79.5534, -22.6146) -> (6.7534, -22.6146)
  circle C1 centre (79.1534, 61.7854) radius 1.875
  circle C2 centre (7.1534, 61.7854) radius 1.875
  arc A1 centre (79.5534, -16.6146) radius 6 clockwise from (85.5534, -16.6146) to (79.5534, -22.6146)
  arc A2 centre (79.5534, 62.1854) radius 6 clockwise from (79.5534, 68.1854) to (85.5534, 62.1854)
  arc A3 centre (71.1534, 61.7854) radius 4 clockwise from (71.1534, 65.7854) to (75.1534, 61.7854)
  arc A4 centre (79.1534, 61.7854) radius 4 clockwise from (79.1534, 57.7854) to (75.1534, 61.7854)
  arc A5 centre (79.1534, 53.7854) radius 4 clockwise from (79.1534, 57.7854) to (83.1534, 53.7854)
  arc A6 centre (79.1534, -8.2146) radius 4 clockwise from (83.1534, -8.2146) to (79.1534, -12.2146)
  arc A7 centre (79.1534, -16.2146) radius 4 clockwise from (75.1534, -16.2146) to (79.1534, -12.2146)
  arc A8 centre (71.1534, -16.2146) radius 4 clockwise from (75.1534, -16.2146) to (71.1534, -20.2146)
  arc A9 centre (15.1534, -16.2146) radius 4 clockwise from (15.1534, -20.2146) to (11.1534, -16.2146)
  arc A10 centre (7.1534, -16.2146) radius 4 clockwise from (7.1534, -12.2146) to (11.1534, -16.2146)
  arc A11 centre (7.1534, -8.2146) radius 4 clockwise from (7.1534, -12.2146) to (3.1534, -8.2146)
  arc A12 centre (7.1534, 53.7854) radius 4 clockwise from (3.1534, 53.7854) to (7.1534, 57.7854)
  arc A13 centre (7.1534, 61.7854) radius 4 clockwise from (11.1534, 61.7854) to (7.1534, 57.7854)
  arc A14 centre (15.1534, 61.7854) radius 4 clockwise from (11.1534, 61.7854) to (15.1534, 65.7854)
  arc A15 centre (6.7534, 62.1854) radius 6 clockwise from (0.7534, 62.1854) to (6.7534, 68.1854)
  arc A16 centre (6.7534, -16.6146) radius 6 clockwise from (6.7534, -22.6146) to (0.7534, -16.6146)
  arc A17 centre (7.1534, -16.2146) radius 4 clockwise from (7.1534, -12.2146) to (11.1534, -16.2146)
  arc A18 centre (79.1534, -16.2146) radius 4 clockwise from (75.1534, -16.2146) to (79.1534, -12.2146)
  circle C3 centre (7.1534, -16.2146) radius 1.725
  circle C4 centre (79.1534, -16.2146) radius 1.725
extrude "Estrusione12" cut sketch "Schizzo11" profile of C3 C4 against normal blind 1580.295
sketch "Schizzo12" plane through (0, 0, 68.1854) normal (0, 0, 1) x axis (-1, 0, 0)
  line L1 (6.7534, -5.4136) -> (35.6534, -5.4136)
  line L2 (6.7534, -25.4136) -> (6.7534, -5.4136)
  line L3 (35.6534, -25.4136) -> (6.7534, -25.4136)
  line L4 (35.6534, -5.4136) -> (35.6534, -25.4136)
  line L5 (49.6534, -7.4136) -> (36.6534, -7.4136)
  line L6 (50.6534, -5.4136) -> (50.6534, -6.4136)
  line L7 (36.6534, -4.4136) -> (49.6534, -4.4136)
  line L8 (35.6534, -6.4136) -> (35.6534, -5.4136)
  line L9 (50.6534, -5.4136) -> (79.5534, -5.4136)
  line L10 (50.6534, -25.4136) -> (50.6534, -5.4136)
  line L11 (79.5534, -25.4136) -> (50.6534, -25.4136)
  line L12 (79.5534, -5.4136) -> (79.5534, -25.4136)
  line L13 (35.6534, -25.4136) -> (50.6534, -25.4136)
  circle C1 centre (48.6534, -5.9136) radius 1.25
  circle C2 centre (37.6534, -5.9136) radius 1.25
  arc A1 centre (36.6534, -6.4136) radius 1 clockwise from (36.6534, -7.4136) to (35.6534, -6.4136)
  arc A2 centre (49.6534, -6.4136) radius 1 clockwise from (50.6534, -6.4136) to (49.6534, -7.4136)
  arc A3 centre (49.6534, -5.4136) radius 1 clockwise from (49.6534, -4.4136) to (50.6534, -5.4136)
  arc A4 centre (36.6534, -5.4136) radius 1 clockwise from (35.6534, -5.4136) to (36.6534, -4.4136)
  point P22 (50.6534, -25.4136)
  point P24 (50.6534, -25.4136)
  point P5 (35.6534, -25.4136)
  point P25 (35.6534, -25.4136)
  coincident P22 P24
  coincident P5 P25
extrude "Estrusione13" add sketch "Schizzo12" profile of L4 A1 L5 A2 L10 L13 against normal blind 2.4
sketch "Schizzo13" plane through (0, 25.4136, 0) normal (0, 1, 0) x axis (-1, 0, 0)
  line L1 (6.7534, 68.1854) -> (79.5534, 68.1854)
  line L2 (0.7534, -16.6146) -> (0.7534, 62.1854)
  line L3 (79.5534, -22.6146) -> (6.7534, -22.6146)
  line L4 (85.5534, 62.1854) -> (85.5534, -16.6146)
  line L5 (71.1534, 65.7854) -> (15.1534, 65.7854)
  line L6 (83.1534, -8.2146) -> (83.1534, 53.7854)
  line L7 (15.1534, -20.2146) -> (71.1534, -20.2146)
  line L8 (3.1534, 53.7854) -> (3.1534, -8.2146)
  line L9 (85.5534, 62.1854) -> (85.5534, -16.6146)
  line L10 (79.5534, -22.6146) -> (6.7534, -22.6146)
  line L11 (0.7534, -16.6146) -> (0.7534, 62.1854)
  line L12 (6.7534, 68.1854) -> (79.5534, 68.1854)
  arc A1 centre (6.7534, 62.1854) radius 6 clockwise from (0.7534, 62.1854) to (6.7534, 68.1854)
  arc A2 centre (6.7534, -16.6146) radius 6 clockwise from (6.7534, -22.6146) to (0.7534, -16.6146)
  arc A3 centre (79.5534, -16.6146) radius 6 clockwise from (85.5534, -16.6146) to (79.5534, -22.6146)
  arc A4 centre (79.5534, 62.1854) radius 6 clockwise from (79.5534, 68.1854) to (85.5534, 62.1854)
  circle C1 centre (7.1534, -16.2146) radius 1.725
  circle C2 centre (79.1534, -16.2146) radius 1.725
  circle C3 centre (79.1534, 61.7854) radius 1.875
  circle C4 centre (7.1534, 61.7854) radius 1.875
  arc A5 centre (71.1534, 61.7854) radius 4 clockwise from (71.1534, 65.7854) to (75.1534, 61.7854)
  arc A6 centre (79.1534, 61.7854) radius 4 clockwise from (79.1534, 57.7854) to (75.1534, 61.7854)
  arc A7 centre (79.1534, 53.7854) radius 4 clockwise from (79.1534, 57.7854) to (83.1534, 53.7854)
  arc A8 centre (79.1534, -8.2146) radius 4 clockwise from (83.1534, -8.2146) to (79.1534, -12.2146)
  arc A9 centre (79.1534, -16.2146) radius 4 clockwise from (75.1534, -16.2146) to (79.1534, -12.2146)
  arc A10 centre (71.1534, -16.2146) radius 4 clockwise from (75.1534, -16.2146) to (71.1534, -20.2146)
  arc A11 centre (15.1534, -16.2146) radius 4 clockwise from (15.1534, -20.2146) to (11.1534, -16.2146)
  arc A12 centre (7.1534, -16.2146) radius 4 clockwise from (7.1534, -12.2146) to (11.1534, -16.2146)
  arc A13 centre (7.1534, -8.2146) radius 4 clockwise from (7.1534, -12.2146) to (3.1534, -8.2146)
  arc A14 centre (7.1534, 53.7854) radius 4 clockwise from (3.1534, 53.7854) to (7.1534, 57.7854)
  arc A15 centre (7.1534, 61.7854) radius 4 clockwise from (11.1534, 61.7854) to (7.1534, 57.7854)
  arc A16 centre (15.1534, 61.7854) radius 4 clockwise from (11.1534, 61.7854) to (15.1534, 65.7854)
  arc A17 centre (79.5534, -16.6146) radius 6 clockwise from (85.5534, -16.6146) to (79.5534, -22.6146)
  arc A18 centre (6.7534, -16.6146) radius 6 clockwise from (6.7534, -22.6146) to (0.7534, -16.6146)
  arc A19 centre (6.7534, 62.1854) radius 6 clockwise from (0.7534, 62.1854) to (6.7534, 68.1854)
  arc A20 centre (79.5534, 62.1854) radius 6 clockwise from (79.5534, 68.1854) to (85.5534, 62.1854)
extrude "Estrusione14" add sketch "Schizzo13" along normal blind 2
sketch "Schizzo14" plane through (-3.1534, 0, 0) normal (-1, 0, 0) x axis (0, -1, 0)
  line L1 (-5.4136, -8.2146) -> (-25.4136, -8.2146)
  line L2 (-5.4136, 53.7854) -> (-5.4136, -8.2146)
  line L3 (-25.4136, 53.7854) -> (-5.4136, 53.7854)
  line L4 (-25.4136, -8.2146) -> (-25.4136, 53.7854)
  line L5 (-5.4136, -20.2146) -> (-25.4136, -20.2146)
  line L6 (-25.4136, -20.2146) -> (-5.4136, -20.2146)
  curve K1 (-17.4136, -20.2146) -> (-5.4136, -20.2146)
  curve K2 (-25.4136, 3.7854) -> (-17.4136, -20.2146)
  curve K3 (-25.4136, 27.7854) -> (-25.4136, 3.7854)
  curve K4 (-25.4136, 27.7854) -> (-5.4136, -20.2146)
  line L7 (-25.4136, -20.2146) -> (-5.4136, -20.2146)
  line L8 (-25.4136, -19.2578) -> (-25.4136, -20.2146)
  line L9 (-25.4136, 27.7854) -> (-25.4136, -19.2578)
  point P8 (-17.4136, -20.2146)
  point P9 (-25.4136, 3.7854)
  point P10 (-25.4136, 27.7854)
  point P7 (-5.4136, -20.2146)
  point P11 (-5.4136, -20.2146)
  point P6 (-25.4136, -20.2146)
  point P12 (-25.4136, -20.2146)
  coincident L6 P8
  coincident L4 P9
  coincident L4 P10
  coincident P7 P11
  coincident P6 P12
  perpendicular L6 L8
  parallel L4 L9
  dimension "d87" distance L6 P10 = 48
  dimension "d88" distance L6 P9 = 24
  dimension "d89" distance P7 P8 = 12
extrude "Estrusione15" add sketch "Schizzo14" profile of L1 L4 L5 L6 K4 L7 L8 L9 to an object
sketch "Schizzo15" plane through (0, 5.4136, 0) normal (0, -1, 0) x axis (1, 0, 0)
  line L1 (-6.7534, -22.6146) -> (-79.5534, -22.6146)
  line L2 (-0.7534, 62.1854) -> (-0.7534, -16.6146)
  line L3 (-35.6534, 68.1854) -> (-6.7534, 68.1854)
  line L4 (-35.6534, 65.7854) -> (-35.6534, 68.1854)
  line L5 (-15.1534, 65.7854) -> (-35.6534, 65.7854)
  line L6 (-3.1534, -8.2146) -> (-3.1534, 53.7854)
  line L7 (-71.1534, -20.2146) -> (-15.1534, -20.2146)
  line L8 (-83.1534, 53.7854) -> (-83.1534, -8.2146)
  line L9 (-50.6534, 65.7854) -> (-71.1534, 65.7854)
  line L10 (-50.6534, 68.1854) -> (-50.6534, 65.7854)
  line L11 (-79.5534, 68.1854) -> (-50.6534, 68.1854)
  line L12 (-85.5534, -16.6146) -> (-85.5534, 62.1854)
  circle C1 centre (-7.1534, -16.2146) radius 1.725
  circle C2 centre (-79.1534, -16.2146) radius 1.725
  circle C3 centre (-79.1534, 61.7854) radius 1.875
  circle C4 centre (-7.1534, 61.7854) radius 1.875
  arc A1 centre (-79.5534, -16.6146) radius 6 clockwise from (-79.5534, -22.6146) to (-85.5534, -16.6146)
  arc A2 centre (-6.7534, -16.6146) radius 6 clockwise from (-0.7534, -16.6146) to (-6.7534, -22.6146)
  arc A3 centre (-6.7534, 62.1854) radius 6 clockwise from (-6.7534, 68.1854) to (-0.7534, 62.1854)
  arc A4 centre (-15.1534, 61.7854) radius 4 clockwise from (-15.1534, 65.7854) to (-11.1534, 61.7854)
  arc A5 centre (-7.1534, 61.7854) radius 4 clockwise from (-7.1534, 57.7854) to (-11.1534, 61.7854)
  arc A6 centre (-7.1534, 53.7854) radius 4 clockwise from (-7.1534, 57.7854) to (-3.1534, 53.7854)
  arc A7 centre (-7.1534, -8.2146) radius 4 clockwise from (-3.1534, -8.2146) to (-7.1534, -12.2146)
  arc A8 centre (-7.1534, -16.2146) radius 4 clockwise from (-11.1534, -16.2146) to (-7.1534, -12.2146)
  arc A9 centre (-15.1534, -16.2146) radius 4 clockwise from (-11.1534, -16.2146) to (-15.1534, -20.2146)
  arc A10 centre (-71.1534, -16.2146) radius 4 clockwise from (-71.1534, -20.2146) to (-75.1534, -16.2146)
  arc A11 centre (-79.1534, -16.2146) radius 4 clockwise from (-79.1534, -12.2146) to (-75.1534, -16.2146)
  arc A12 centre (-79.1534, -8.2146) radius 4 clockwise from (-79.1534, -12.2146) to (-83.1534, -8.2146)
  arc A13 centre (-79.1534, 53.7854) radius 4 clockwise from (-83.1534, 53.7854) to (-79.1534, 57.7854)
  arc A14 centre (-79.1534, 61.7854) radius 4 clockwise from (-75.1534, 61.7854) to (-79.1534, 57.7854)
  arc A15 centre (-71.1534, 61.7854) radius 4 clockwise from (-75.1534, 61.7854) to (-71.1534, 65.7854)
  arc A16 centre (-79.5534, 62.1854) radius 6 clockwise from (-85.5534, 62.1854) to (-79.5534, 68.1854)
  circle C5 centre (-7.1534, -16.2146) radius 1.725
  circle C6 centre (-79.1534, -16.2146) radius 1.725
extrude "Estrusione16" cut sketch "Schizzo15" profile of C1 C2 C5 C6 against normal blind 20
fillet "Raccordo4" radius 20
fillet "Raccordo5" radius 1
